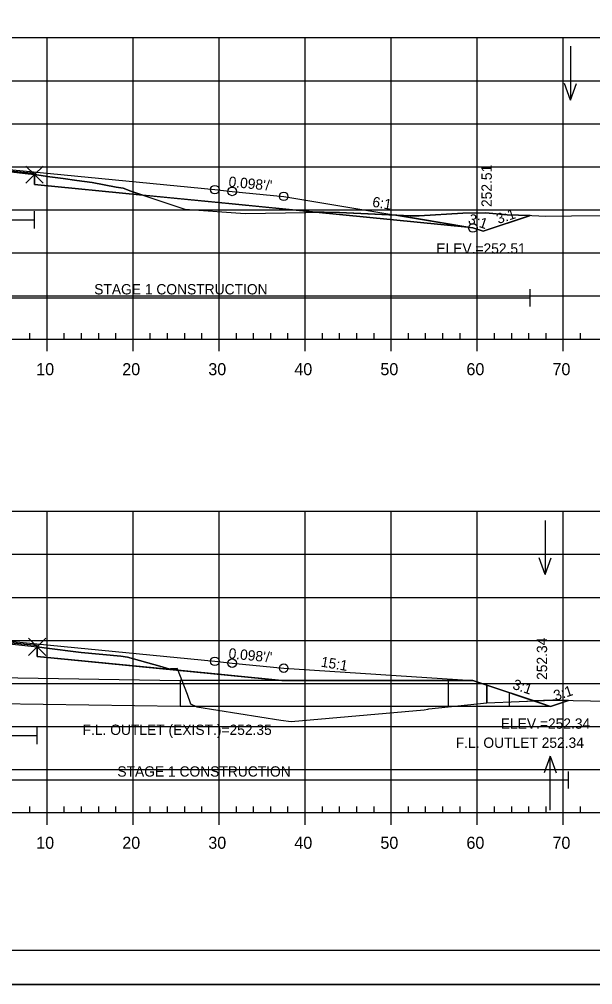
# Model space of a CAD drawing. Extents: x 1365647 to 1367999, y 387113 to 400173.
# Drawn here: x 1365900.9 to 1365967.5, y 391426.2 to 391538.3 of the extents above; entities that cross this region are included whole.
import ezdxf

# ---------------------------------------------------------------- set-up
doc = ezdxf.new("R2010")
doc.units = 0
for name, color, linetype in [('R_Alt Surface', 7, 'Continuous'), ('R_Axis', 7, 'Continuous'), ('R_Axis Annot', 7, 'Continuous'), ('R_Border', 7, 'Continuous'), ('R_Border Notes', 7, 'Continuous'), ('R_Contours', 7, 'Continuous'), ('R_Exist Surface', 7, 'Continuous'), ('R_Fin Surface', 7, 'Continuous'), ('R_Fin Surface Annot', 7, 'Continuous'), ('R_Grid', 7, 'Continuous'), ('R_No Plot', 7, 'Continuous'), ('R_Proposed Const Limits', 7, 'Continuous'), ('R_Water', 7, 'Continuous'), ('R_Water Annot', 7, 'Continuous')]:
    doc.layers.add(name, color=color, linetype=linetype)

msp = doc.modelspace()

# ---------------------------------------------------------------- linework, layer by layer
at = {"layer": 'R_Alt Surface'}
for points in [[(1365841.78, 391522.59), (1365862.59, 391523), (1365878.63, 391521.43), (1365878.63, 391522.72), (1365894.09, 391521.21), (1365902.63, 391520.37), (1365902.63, 391519.08), (1365925.59, 391516.83), (1365953.01, 391514.13)], [(1365841.78, 391467.81), (1365862.59, 391468.22), (1365879.07, 391466.61), (1365879.07, 391467.9), (1365894.09, 391466.43), (1365902.93, 391465.56), (1365902.93, 391464.27), (1365931.38, 391461.48), (1365953.59, 391461.48)]]:
    msp.add_lwpolyline(points, dxfattribs=at)
at = {"layer": 'R_Axis'}
for p, q in [((1365902.09, 391501.14), (1365902.09, 391501.84)), ((1365906.09, 391501.14), (1365906.09, 391501.84)), ((1365908.09, 391501.14), (1365908.09, 391501.84)), ((1365910.09, 391501.14), (1365910.09, 391501.84)), ((1365912.09, 391501.14), (1365912.09, 391501.84)), ((1365916.09, 391501.14), (1365916.09, 391501.84)), ((1365918.09, 391501.14), (1365918.09, 391501.84)), ((1365920.09, 391501.14), (1365920.09, 391501.84)), ((1365922.09, 391501.14), (1365922.09, 391501.84)), ((1365926.09, 391501.14), (1365926.09, 391501.84)), ((1365928.09, 391501.14), (1365928.09, 391501.84)), ((1365930.09, 391501.14), (1365930.09, 391501.84)), ((1365932.09, 391501.14), (1365932.09, 391501.84)), ((1365936.09, 391501.14), (1365936.09, 391501.84)), ((1365938.09, 391501.14), (1365938.09, 391501.84)), ((1365940.09, 391501.14), (1365940.09, 391501.84)), ((1365942.09, 391501.14), (1365942.09, 391501.84)), ((1365946.09, 391501.14), (1365946.09, 391501.84)), ((1365948.09, 391501.14), (1365948.09, 391501.84)), ((1365950.09, 391501.14), (1365950.09, 391501.84)), ((1365952.09, 391501.14), (1365952.09, 391501.84)), ((1365956.09, 391501.14), (1365956.09, 391501.84)), ((1365958.09, 391501.14), (1365958.09, 391501.84)), ((1365960.09, 391501.14), (1365960.09, 391501.84)), ((1365962.09, 391501.14), (1365962.09, 391501.84)), ((1365966.09, 391501.14), (1365966.09, 391501.84)), ((1365749.09, 391501.14), (1366039.09, 391501.14)), ((1365904.09, 391499.74), (1365904.09, 391501.14)), ((1365914.09, 391499.74), (1365914.09, 391501.14)), ((1365924.09, 391499.74), (1365924.09, 391501.14)), ((1365934.09, 391499.74), (1365934.09, 391501.14)), ((1365944.09, 391499.74), (1365944.09, 391501.14)), ((1365954.09, 391499.74), (1365954.09, 391501.14)), ((1365964.09, 391499.74), (1365964.09, 391501.14)), ((1365902.09, 391446.14), (1365902.09, 391446.84)), ((1365906.09, 391446.14), (1365906.09, 391446.84)), ((1365908.09, 391446.14), (1365908.09, 391446.84)), ((1365910.09, 391446.14), (1365910.09, 391446.84)), ((1365912.09, 391446.14), (1365912.09, 391446.84)), ((1365916.09, 391446.14), (1365916.09, 391446.84)), ((1365918.09, 391446.14), (1365918.09, 391446.84)), ((1365920.09, 391446.14), (1365920.09, 391446.84)), ((1365922.09, 391446.14), (1365922.09, 391446.84)), ((1365926.09, 391446.14), (1365926.09, 391446.84)), ((1365928.09, 391446.14), (1365928.09, 391446.84)), ((1365930.09, 391446.14), (1365930.09, 391446.84)), ((1365932.09, 391446.14), (1365932.09, 391446.84)), ((1365936.09, 391446.14), (1365936.09, 391446.84)), ((1365938.09, 391446.14), (1365938.09, 391446.84)), ((1365940.09, 391446.14), (1365940.09, 391446.84)), ((1365942.09, 391446.14), (1365942.09, 391446.84)), ((1365946.09, 391446.14), (1365946.09, 391446.84)), ((1365948.09, 391446.14), (1365948.09, 391446.84)), ((1365950.09, 391446.14), (1365950.09, 391446.84)), ((1365952.09, 391446.14), (1365952.09, 391446.84)), ((1365956.09, 391446.14), (1365956.09, 391446.84)), ((1365958.09, 391446.14), (1365958.09, 391446.84)), ((1365960.09, 391446.14), (1365960.09, 391446.84)), ((1365962.09, 391446.14), (1365962.09, 391446.84)), ((1365966.09, 391446.14), (1365966.09, 391446.84)), ((1365749.09, 391446.14), (1366039.09, 391446.14)), ((1365904.09, 391444.74), (1365904.09, 391446.14)), ((1365914.09, 391444.74), (1365914.09, 391446.14)), ((1365924.09, 391444.74), (1365924.09, 391446.14)), ((1365934.09, 391444.74), (1365934.09, 391446.14)), ((1365944.09, 391444.74), (1365944.09, 391446.14)), ((1365954.09, 391444.74), (1365954.09, 391446.14)), ((1365964.09, 391444.74), (1365964.09, 391446.14))]:
    msp.add_line(p, q, dxfattribs=at)
at = {"layer": 'R_Border'}
msp.add_line((1366052.27, 391430.14), (1365736.09, 391430.14), dxfattribs=at)
at = {"layer": 'R_Contours'}
for p, q in [((1365902.63, 391520.23), (1365902.63, 391519.08)), ((1365902.63, 391519.08), (1365915.23, 391517.85)), ((1365935.34, 391515.87), (1365953.01, 391514.13)), ((1365944.75, 391515.51), (1365953.01, 391514.13)), ((1365953.01, 391514.13), (1365944.75, 391515.51)), ((1365902.93, 391465.39), (1365902.93, 391464.27)), ((1365902.93, 391464.27), (1365919.28, 391462.67)), ((1365960.7, 391459.11), (1365962.6, 391458.48)), ((1365962.6, 391458.48), (1365964.68, 391459.17))]:
    msp.add_line(p, q, dxfattribs=at)
for points in [[(1365878.63, 391522.2), (1365879.05, 391522.18), (1365879.6, 391522.16), (1365882.58, 391521.99), (1365883.79, 391521.93), (1365884.47, 391521.88), (1365885.34, 391521.84), (1365886.71, 391521.69), (1365888.6, 391521.55), (1365890.09, 391521.47), (1365890.4, 391521.44), (1365890.63, 391521.42), (1365891.23, 391521.36), (1365892.54, 391521.23), (1365894.29, 391521.06), (1365895.72, 391520.92), (1365898.22, 391520.69), (1365899.34, 391520.59), (1365900.22, 391520.51), (1365901.54, 391520.37), (1365902.63, 391520.23), (1365902.63, 391520.37), (1365894.09, 391521.21), (1365878.63, 391522.72)], [(1365902.63, 391520.23), (1365904.43, 391519.97), (1365905.95, 391519.78), (1365907.54, 391519.57), (1365909.32, 391519.32), (1365912.13, 391518.79), (1365912.94, 391518.67), (1365913.82, 391518.32), (1365915.23, 391517.85), (1365902.63, 391519.08)], [(1365915.23, 391517.85), (1365920.12, 391516.22), (1365920.65, 391516.18), (1365926.02, 391515.81), (1365927.12, 391515.72), (1365934.18, 391515.85), (1365935.34, 391515.87), (1365925.59, 391516.83)], [(1365935.34, 391515.87), (1365936.3, 391515.89), (1365938.09, 391515.84), (1365946.29, 391515.44), (1365947.34, 391515.43), (1365952.43, 391515.76), (1365955.04, 391515.81), (1365957.55, 391515.57), (1365958.9, 391515.51), (1365960.25, 391515.47), (1365954.77, 391513.65), (1365953.59, 391514.04), (1365953.01, 391514.13)], [(1365879.07, 391467.37), (1365879.61, 391467.36), (1365880.06, 391467.33), (1365881.54, 391467.25), (1365882.32, 391467.22), (1365887.48, 391466.86), (1365888.9, 391466.74), (1365890.44, 391466.66), (1365890.9, 391466.64), (1365890.97, 391466.63), (1365891, 391466.63), (1365893.34, 391466.35), (1365895.06, 391466.19), (1365896.08, 391466.11), (1365898.57, 391465.87), (1365900.07, 391465.71), (1365902.93, 391465.39), (1365902.93, 391465.56), (1365894.09, 391466.43), (1365879.07, 391467.9)], [(1365902.93, 391465.39), (1365903.75, 391465.28), (1365908.06, 391464.75), (1365912.66, 391464.32), (1365913.43, 391464.21), (1365917.21, 391463.15), (1365918.35, 391462.81), (1365918.43, 391462.83), (1365919.2, 391462.88), (1365919.28, 391462.67), (1365902.93, 391464.27)], [(1365919.28, 391462.67), (1365920.36, 391459.88), (1365920.75, 391458.78), (1365921.48, 391458.41), (1365931.26, 391456.89), (1365932.46, 391456.74), (1365947.93, 391458.09), (1365948.34, 391458.15), (1365948.45, 391458.21), (1365955.22, 391458.9), (1365955.22, 391460.94), (1365953.59, 391461.48), (1365948.45, 391461.48), (1365931.38, 391461.48)], [(1365955.22, 391460.94), (1365955.22, 391458.9), (1365958.94, 391459.05), (1365960.7, 391459.11)], [(1365960.7, 391459.11), (1365962.88, 391459.19), (1365963.21, 391459.2), (1365964.68, 391459.17), (1365962.6, 391458.48)]]:
    msp.add_lwpolyline(points, close=True, dxfattribs=at)
for points in [[(1365915.23, 391517.85), (1365913.82, 391518.32), (1365912.94, 391518.67), (1365912.13, 391518.79), (1365909.32, 391519.32), (1365907.54, 391519.57), (1365905.95, 391519.78), (1365904.43, 391519.97), (1365902.63, 391520.23)], [(1365944.75, 391515.51), (1365938.09, 391515.84), (1365936.3, 391515.89), (1365935.34, 391515.87)], [(1365960.25, 391515.47), (1365958.9, 391515.51), (1365957.55, 391515.57), (1365955.04, 391515.81), (1365952.43, 391515.76), (1365947.34, 391515.43), (1365946.29, 391515.44), (1365944.75, 391515.51)], [(1365953.01, 391514.13), (1365953.59, 391514.04), (1365954.77, 391513.65), (1365960.25, 391515.47)], [(1365919.28, 391462.67), (1365919.2, 391462.88), (1365918.43, 391462.83), (1365918.35, 391462.81), (1365917.21, 391463.15), (1365913.43, 391464.21), (1365912.66, 391464.32), (1365908.06, 391464.75), (1365903.75, 391465.28), (1365902.93, 391465.39)], [(1365964.68, 391459.17), (1365963.21, 391459.2), (1365962.88, 391459.19), (1365960.7, 391459.11)]]:
    msp.add_lwpolyline(points, dxfattribs=at)
at = {"layer": 'R_Exist Surface'}
for points in [[(1365900.22, 391520.51), (1365901.54, 391520.37), (1365902.63, 391520.23), (1365904.43, 391519.97), (1365905.95, 391519.78), (1365907.54, 391519.57), (1365909.32, 391519.32), (1365912.13, 391518.79), (1365912.94, 391518.67), (1365913.82, 391518.32), (1365920.12, 391516.22), (1365920.65, 391516.18), (1365926.02, 391515.81), (1365927.12, 391515.72), (1365934.18, 391515.85), (1365936.3, 391515.89), (1365938.09, 391515.84), (1365946.29, 391515.44), (1365947.34, 391515.43), (1365952.43, 391515.76), (1365955.04, 391515.81), (1365957.55, 391515.57), (1365958.9, 391515.51), (1365960.45, 391515.47), (1365962.06, 391515.4), (1365965.05, 391515.44), (1365970.28, 391515.47)], [(1365900.07, 391465.71), (1365902.93, 391465.39), (1365903.75, 391465.28), (1365908.06, 391464.75), (1365912.66, 391464.32), (1365913.43, 391464.21), (1365917.21, 391463.15), (1365918.35, 391462.81), (1365918.43, 391462.83), (1365919.2, 391462.88), (1365920.36, 391459.88), (1365920.75, 391458.78), (1365921.48, 391458.41), (1365931.26, 391456.89), (1365932.46, 391456.74), (1365947.93, 391458.09), (1365948.34, 391458.15), (1365948.45, 391458.21)], [(1365955.22, 391458.9), (1365958.94, 391459.05), (1365962.88, 391459.19), (1365963.21, 391459.2), (1365973.35, 391459), (1365975.38, 391459.03), (1365977.52, 391458.99), (1365982.82, 391458.85), (1365986.67, 391458.81), (1365997.68, 391458.79), (1365998.45, 391458.79), (1365999.17, 391458.79), (1366009.2, 391458.83), (1366010.56, 391458.83), (1366018.83, 391458.88), (1366019.65, 391458.88), (1366026.45, 391458.88), (1366033.65, 391458.88), (1366039.09, 391458.83)]]:
    msp.add_lwpolyline(points, dxfattribs=at)
at = {"layer": 'R_Fin Surface'}
for points in [[(1365813.65, 391516.94), (1365817.45, 391515.67), (1365834.59, 391521.39), (1365841.78, 391522.59), (1365856.59, 391525.06), (1365862.59, 391524.47), (1365864.59, 391524.27), (1365894.09, 391521.38), (1365923.59, 391518.49), (1365925.59, 391518.29), (1365931.59, 391517.71), (1365953.01, 391514.13), (1365953.59, 391514.04), (1365954.77, 391513.65), (1365960.25, 391515.47)], [(1365820.75, 391516.78), (1365834.59, 391521.39), (1365847.47, 391523.54), (1365856.59, 391525.06), (1365862.59, 391524.47), (1365864.59, 391524.27), (1365894.09, 391521.38), (1365923.59, 391518.49), (1365925.59, 391518.29), (1365931.59, 391517.71)], [(1365856.59, 391525.06), (1365862.59, 391524.47), (1365864.59, 391524.27), (1365894.09, 391521.38), (1365923.59, 391518.49), (1365925.59, 391518.29), (1365931.59, 391517.71)], [(1365810.98, 391460.24), (1365813.23, 391459.49), (1365834.59, 391466.61), (1365841.78, 391467.81), (1365856.59, 391470.27), (1365862.59, 391469.69), (1365864.59, 391469.49), (1365894.09, 391466.6), (1365923.59, 391463.71), (1365925.59, 391463.51), (1365931.59, 391462.92), (1365953.59, 391461.48), (1365962.6, 391458.48), (1365964.68, 391459.17)], [(1365856.59, 391470.27), (1365862.59, 391469.69), (1365864.59, 391469.49), (1365894.09, 391466.6), (1365923.59, 391463.71), (1365925.59, 391463.51), (1365931.59, 391462.92)]]:
    msp.add_lwpolyline(points, dxfattribs=at)
at = {"layer": 'R_Grid'}
for p, q in [((1365749.09, 391536.14), (1366039.09, 391536.14)), ((1365904.09, 391501.14), (1365904.09, 391536.14)), ((1365914.09, 391501.14), (1365914.09, 391536.14)), ((1365924.09, 391501.14), (1365924.09, 391536.14)), ((1365934.09, 391501.14), (1365934.09, 391536.14)), ((1365944.09, 391501.14), (1365944.09, 391536.14)), ((1365954.09, 391501.14), (1365954.09, 391536.14)), ((1365964.09, 391501.14), (1365964.09, 391536.14)), ((1365749.09, 391531.14), (1366039.09, 391531.14)), ((1365749.09, 391526.14), (1366039.09, 391526.14)), ((1365749.09, 391521.14), (1366039.09, 391521.14)), ((1365749.09, 391516.14), (1366039.09, 391516.14)), ((1365749.09, 391511.14), (1366039.09, 391511.14)), ((1365749.09, 391506.14), (1366039.09, 391506.14)), ((1365749.09, 391501.14), (1366039.09, 391501.14)), ((1365749.09, 391481.14), (1366039.09, 391481.14)), ((1365904.09, 391446.14), (1365904.09, 391481.14)), ((1365914.09, 391446.14), (1365914.09, 391481.14)), ((1365924.09, 391446.14), (1365924.09, 391481.14)), ((1365934.09, 391446.14), (1365934.09, 391481.14)), ((1365944.09, 391446.14), (1365944.09, 391481.14)), ((1365954.09, 391446.14), (1365954.09, 391481.14)), ((1365964.09, 391446.14), (1365964.09, 391481.14)), ((1365749.09, 391476.14), (1366039.09, 391476.14)), ((1365749.09, 391471.14), (1366039.09, 391471.14)), ((1365749.09, 391466.14), (1366039.09, 391466.14)), ((1365749.09, 391461.14), (1365919.54, 391461.14)), ((1365749.09, 391461.14), (1366039.09, 391461.14)), ((1365749.09, 391456.14), (1366039.09, 391456.14)), ((1365749.09, 391451.14), (1366039.09, 391451.14)), ((1365749.09, 391446.14), (1366039.09, 391446.14))]:
    msp.add_line(p, q, dxfattribs=at)
at = {"layer": 'R_No Plot'}
msp.add_line((1365723.69, 391426.16), (1366057.03, 391426.16), dxfattribs=at)
msp.add_lwpolyline([(1365723.69, 391639.49), (1366057.03, 391639.49), (1366057.03, 391426.16), (1365723.69, 391426.16)], close=True, dxfattribs=at)
for points in [[(1365902.63, 391520.23), (1365901.63, 391521.23), (1365902.63, 391520.23), (1365901.63, 391519.23), (1365902.63, 391520.23), (1365903.63, 391519.23), (1365902.63, 391520.23), (1365903.63, 391521.23)], [(1365902.93, 391465.39), (1365901.93, 391466.39), (1365902.93, 391465.39), (1365901.93, 391464.39), (1365902.93, 391465.39), (1365903.93, 391464.39), (1365902.93, 391465.39), (1365903.93, 391466.39)]]:
    msp.add_lwpolyline(points, dxfattribs=at)
for centre in [(1365923.59, 391518.49), (1365923.59, 391518.49), (1365923.59, 391518.49), (1365923.59, 391518.49), (1365923.59, 391518.49), (1365925.59, 391518.29), (1365925.59, 391518.29), (1365925.59, 391518.29), (1365925.59, 391518.29), (1365925.59, 391518.29), (1365931.59, 391517.71), (1365931.59, 391517.71), (1365931.59, 391517.71), (1365931.59, 391517.71), (1365931.59, 391517.71), (1365953.59, 391514.04), (1365953.59, 391514.04), (1365953.59, 391514.04), (1365953.59, 391514.04), (1365953.59, 391514.04), (1365923.59, 391463.71), (1365923.59, 391463.71), (1365923.59, 391463.71), (1365923.59, 391463.71), (1365923.59, 391463.71), (1365925.59, 391463.51), (1365925.59, 391463.51), (1365925.59, 391463.51), (1365925.59, 391463.51), (1365925.59, 391463.51), (1365931.59, 391462.92), (1365931.59, 391462.92), (1365931.59, 391462.92), (1365931.59, 391462.92), (1365931.59, 391462.92)]:
    msp.add_circle(centre, 0.5, dxfattribs=at)
at = {"layer": 'R_Proposed Const Limits'}
msp.add_lwpolyline([(1365954.76, 391513.65), (1365960.16, 391515.45)], dxfattribs=at)
at = {"layer": 'R_Water'}
for p, q in [((1365902.63, 391513.98), (1365902.63, 391515.98)), ((1365878.63, 391514.98), (1365902.63, 391514.98)), ((1365960.25, 391504.93), (1365960.25, 391506.93)), ((1365878.63, 391505.93), (1365960.25, 391505.93)), ((1365857.39, 391462.46), (1365919.54, 391461.49)), ((1365919.54, 391461.49), (1365919.55, 391458.49)), ((1365953.59, 391461.48), (1365919.54, 391461.48)), ((1365950.7, 391461.49), (1365950.7, 391458.48)), ((1365957.79, 391460.08), (1365957.79, 391458.47)), ((1365857.34, 391459.46), (1365919.55, 391458.49)), ((1365962.59, 391458.48), (1365919.54, 391458.48)), ((1365902.93, 391454.08), (1365902.93, 391456.08)), ((1365879.07, 391455.08), (1365902.93, 391455.08)), ((1365964.68, 391448.93), (1365964.68, 391450.93)), ((1365879.07, 391449.93), (1365964.68, 391449.93))]:
    msp.add_line(p, q, dxfattribs=at)
at = {"layer": 'R_Water Annot'}
for p, q in [((1365964.93, 391535.16), (1365964.93, 391528.88)), ((1365964.93, 391528.88), (1365964.23, 391530.8)), ((1365964.93, 391528.88), (1365965.63, 391530.8)), ((1365961.97, 391480.08), (1365961.97, 391473.79)), ((1365961.97, 391473.79), (1365961.27, 391475.72)), ((1365961.97, 391473.79), (1365962.67, 391475.72)), ((1365962.57, 391452.69), (1365961.87, 391450.77)), ((1365962.57, 391446.41), (1365962.57, 391452.69)), ((1365962.57, 391452.69), (1365963.27, 391450.77))]:
    msp.add_line(p, q, dxfattribs=at)

# ---------------------------------------------------------------- texts
at = {"layer": 'R_Axis Annot'}
for s, p in [('10', (1365902.83, 391496.94)), ('20', (1365912.83, 391496.94)), ('30', (1365922.83, 391496.94)), ('40', (1365932.83, 391496.94)), ('50', (1365942.83, 391496.94)), ('60', (1365952.83, 391496.94)), ('70', (1365962.83, 391496.94)), ('10', (1365902.83, 391441.94)), ('20', (1365912.83, 391441.94)), ('30', (1365922.83, 391441.94)), ('40', (1365932.83, 391441.94)), ('50', (1365942.83, 391441.94)), ('60', (1365952.83, 391441.94)), ('70', (1365962.83, 391441.94))]:
    msp.add_text(s, height=1.4, dxfattribs=at).set_placement(p)
at = {"layer": 'R_Border Notes'}
for s, p in [('ELEV.=252.51', (1365949.33, 391511.05)), ('F.L. OUTLET (EXIST.)=252.35', (1365908.22, 391455.16)), ('ELEV.=252.34', (1365956.82, 391455.88))]:
    msp.add_text(s, height=1.2, dxfattribs=at).set_placement(p)
at = {"layer": 'R_Fin Surface Annot'}
for s, rotation, p in [('252.51', 90, (1365955.78, 391516.47)), ("0.098'/'", 354.4029, (1365925.14, 391518.84)), ('6:1', 350.5377, (1365941.83, 391516.51)), ('3:1', 18.4349, (1365956.54, 391514.49)), ('3:1', 341.5651, (1365952.94, 391514.6)), ('252.34', 90, (1365962.21, 391461.55)), ("0.098'/'", 354.4029, (1365925.14, 391464.06)), ('15:1', 350.5377, (1365935.85, 391463.1)), ('3:1', 341.5651, (1365958.11, 391460.54)), ('3:1', 18.4349, (1365963.19, 391459.11))]:
    msp.add_text(s, height=1.2, rotation=rotation, dxfattribs=at).set_placement(p)
at = {"layer": 'R_Water'}
for s, p in [('STAGE 1 CONSTRUCTION', (1365909.57, 391506.32)), ('F.L. OUTLET 252.34', (1365951.59, 391453.66)), ('STAGE 1 CONSTRUCTION', (1365912.26, 391450.32))]:
    msp.add_text(s, height=1.2, dxfattribs=at).set_placement(p)

doc.saveas('drawing.dxf')
